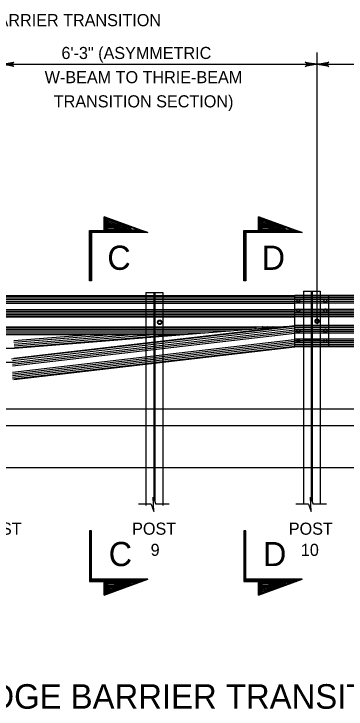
# Model space of a CAD drawing. Extents: x 632007860 to 635435983, y 295418622 to 297794622.
# Drawn here: x 632367530 to 632449960, y 296174617 to 296347078 of the extents above; entities that cross this region are included whole.
import ezdxf

# ---------------------------------------------------------------- set-up
doc = ezdxf.new("R2010")
doc.units = 0
for name, color, linetype in [('S-ABUT', 7, 'Continuous'), ('S-DETL-DIMS', 7, 'Continuous'), ('S-DETL-T120', 7, 'Continuous'), ('S-DETL-T175', 7, 'Continuous'), ('S-DETL-T240', 7, 'Continuous'), ('S-GRND-MAJR', 7, 'Continuous'), ('S-MISC-CNTR-WT01', 7, 'Continuous'), ('S-STEL', 7, 'Continuous')]:
    doc.layers.add(name, color=color, linetype=linetype)

msp = doc.modelspace()

# ---------------------------------------------------------------- linework, layer by layer
at = {"layer": 'S-ABUT'}
for p, q in [((632118834, 296249115), (632656122, 296249115)), ((632141627, 296234532), (632656122, 296234532))]:
    msp.add_line(p, q, dxfattribs=at)
at = {"layer": 'S-DETL-DIMS'}
for p, q in [((632130592, 296334582), (632596456, 296334582)), ((632401549, 296225427), (632398423, 296225427)), ((632406049, 296225427), (632402720, 296225427)), ((632440609, 296225427), (632437484, 296225427)), ((632445109, 296225427), (632441781, 296225427))]:
    msp.add_line(p, q, dxfattribs=at)
for points in [[(632364632, 296334582), (632367545, 296335128), (632367320, 296334973), (632367205, 296334778), (632367171, 296334582), (632367205, 296334387), (632367320, 296334192), (632367545, 296334036), (632364632, 296334582), (632367320, 296334192), (632367205, 296334387), (632364632, 296334582), (632367171, 296334582), (632367205, 296334778), (632364632, 296334582), (632367320, 296334973)], [(632442753, 296334582), (632439841, 296334036), (632440065, 296334192), (632440181, 296334387), (632440214, 296334582), (632440181, 296334778), (632440065, 296334973), (632439841, 296335128), (632442753, 296334582), (632440065, 296334973), (632440181, 296334778), (632442753, 296334582), (632440214, 296334582), (632440181, 296334387), (632442753, 296334582), (632440065, 296334192)], [(632442753, 296334582), (632445666, 296335128), (632445441, 296334973), (632445326, 296334778), (632445292, 296334582), (632445326, 296334387), (632445441, 296334192), (632445666, 296334036), (632442753, 296334582), (632445441, 296334192), (632445326, 296334387), (632442753, 296334582), (632445292, 296334582), (632445326, 296334778), (632442753, 296334582), (632445441, 296334973)], [(632386546, 296280833), (632386546, 296293072), (632400021, 296293072), (632400737, 296292812), (632386807, 296292812), (632386807, 296280833), (632386286, 296280833), (632386286, 296293332), (632399306, 296293332), (632389931, 296296745), (632389931, 296293332), (632400737, 296292812), (632390267, 296296326), (632390244, 296293583), (632398247, 296293493), (632390549, 296295965), (632390549, 296293876), (632396644, 296293786), (632390843, 296295592), (632390854, 296294192), (632395583, 296293955), (632391125, 296295197), (632391136, 296294452), (632394184, 296294204), (632391373, 296294937), (632391407, 296294621), (632393066, 296294430), (632391379, 296294782), (632389931, 296296745), (632389931, 296293332), (632391407, 296294621), (632400737, 296292812)], [(632424835, 296280833), (632424835, 296293072), (632438310, 296293072), (632439026, 296292812), (632425095, 296292812), (632425095, 296280833), (632424575, 296280833), (632424575, 296293332), (632437595, 296293332), (632428220, 296296745), (632428220, 296293332), (632439026, 296292812), (632428556, 296296326), (632428533, 296293583), (632436536, 296293493), (632428838, 296295965), (632428838, 296293876), (632434933, 296293786), (632429131, 296295592), (632429143, 296294192), (632433872, 296293955), (632429414, 296295197), (632429425, 296294452), (632432473, 296294204), (632429662, 296294937), (632429696, 296294621), (632431355, 296294430), (632429668, 296294782), (632428220, 296296745), (632428220, 296293332), (632429696, 296294621), (632439026, 296292812)], [(632401549, 296225427), (632402262, 296223669), (632402049, 296227184), (632402720, 296225427)], [(632440609, 296225427), (632441323, 296223669), (632441110, 296227184), (632441781, 296225427)], [(632386546, 296218805), (632386546, 296206566), (632400021, 296206566), (632400737, 296206826), (632386807, 296206826), (632386807, 296218805), (632386286, 296218805), (632386286, 296206305), (632399306, 296206305), (632389931, 296202893), (632389931, 296206305), (632400737, 296206826), (632390267, 296203312), (632390244, 296206055), (632398247, 296206145), (632390549, 296203673), (632390549, 296205761), (632396644, 296205852), (632390843, 296204046), (632390854, 296205445), (632395583, 296205682), (632391125, 296204441), (632391136, 296205186), (632394184, 296205434), (632391373, 296204700), (632391407, 296205016), (632393066, 296205208), (632391379, 296204856), (632389931, 296202893), (632389931, 296206305), (632391407, 296205016), (632400737, 296206826)], [(632424835, 296218805), (632424835, 296206566), (632438310, 296206566), (632439026, 296206826), (632425095, 296206826), (632425095, 296218805), (632424575, 296218805), (632424575, 296206305), (632437595, 296206305), (632428220, 296202893), (632428220, 296206305), (632439026, 296206826), (632428556, 296203312), (632428533, 296206055), (632436536, 296206145), (632428838, 296203673), (632428838, 296205761), (632434933, 296205852), (632429131, 296204046), (632429143, 296205445), (632433872, 296205682), (632429414, 296204441), (632429425, 296205186), (632432473, 296205434), (632429662, 296204700), (632429696, 296205016), (632431355, 296205208), (632429668, 296204856), (632428220, 296202893), (632428220, 296206305), (632429696, 296205016), (632439026, 296206826)]]:
    msp.add_lwpolyline(points, dxfattribs=at)
for points in [[(632386807, 296280833), (632386286, 296280833), (632386286, 296293332), (632389931, 296293332), (632389931, 296296745), (632400737, 296292812), (632386807, 296292812)], [(632425095, 296280833), (632424575, 296280833), (632424575, 296293332), (632428220, 296293332), (632428220, 296296745), (632439026, 296292812), (632425095, 296292812)], [(632386807, 296218805), (632386286, 296218805), (632386286, 296206305), (632389931, 296206305), (632389931, 296202893), (632400737, 296206826), (632386807, 296206826)], [(632425095, 296218805), (632424575, 296218805), (632424575, 296206305), (632428220, 296206305), (632428220, 296202893), (632439026, 296206826), (632425095, 296206826)]]:
    msp.add_lwpolyline(points, close=True, dxfattribs=at)
at = {"layer": 'S-GRND-MAJR'}
msp.add_line((632118834, 296244949), (632656122, 296244949), dxfattribs=at)
at = {"layer": 'S-MISC-CNTR-WT01'}
for p, q in [((632442753, 296270859), (632442753, 296337520)), ((632442753, 296271714), (632442753, 296270148)), ((632439264, 296266278), (632443559, 296266278))]:
    msp.add_line(p, q, dxfattribs=at)
at = {"layer": 'S-STEL'}
for p, q in [((632400302, 296277997), (632404470, 296277997)), ((632400302, 296277997), (632400302, 296276955)), ((632402256, 296277997), (632402256, 296226558)), ((632402516, 296277997), (632402516, 296226047)), ((632404470, 296277997), (632404470, 296276955)), ((632439363, 296278280), (632443530, 296278280)), ((632439363, 296278280), (632439363, 296277238)), ((632441317, 296278280), (632441317, 296226558)), ((632441577, 296278280), (632441577, 296226047)), ((632443530, 296278280), (632443530, 296277238)), ((632118834, 296277239), (632437249, 296277239)), ((632118834, 296277070), (632437249, 296277070)), ((632118834, 296276648), (632437249, 296276648)), ((632118834, 296276227), (632437249, 296276227)), ((632400302, 296276955), (632400302, 296260215)), ((632404470, 296276955), (632404470, 296260699)), ((632647109, 296276648), (632437222, 296276648)), ((632647109, 296277239), (632437249, 296277239)), ((632437249, 296271927), (632437249, 296277239)), ((632647109, 296277070), (632437249, 296277070)), ((632647109, 296276648), (632437249, 296276648)), ((632647109, 296276227), (632437249, 296276227)), ((632437949, 296276227), (632438267, 296276227)), ((632439363, 296277238), (632439363, 296264508)), ((632443530, 296277238), (632443530, 296264508)), ((632444944, 296276227), (632444626, 296276227)), ((632445644, 296264508), (632445644, 296277239)), ((632118834, 296275721), (632437249, 296275721)), ((632118834, 296275299), (632437249, 296275299)), ((632647389, 296275721), (632437249, 296275721)), ((632647007, 296275299), (632437249, 296275299)), ((632438284, 296275444), (632437966, 296275444)), ((632444658, 296275444), (632444976, 296275444)), ((632118834, 296273782), (632437249, 296273782)), ((632118834, 296273360), (632437249, 296273360)), ((632118834, 296272939), (632437249, 296272939)), ((632118834, 296272517), (632437249, 296272517)), ((632647109, 296273782), (632437249, 296273782)), ((632647109, 296273360), (632437249, 296273360)), ((632647109, 296272939), (632437249, 296272939)), ((632647109, 296272517), (632437249, 296272517)), ((632438267, 296273023), (632437949, 296273023)), ((632437966, 296273821), (632438284, 296273821)), ((632444976, 296273821), (632444658, 296273821)), ((632444658, 296273039), (632444976, 296273039)), ((632118834, 296272096), (632437249, 296272096)), ((632118834, 296271965), (632437249, 296271927)), ((632403809, 296271045), (632403576, 296271045)), ((632403809, 296271045), (632403576, 296271045)), ((632647109, 296272096), (632437249, 296272096)), ((632647109, 296271927), (632437249, 296271927)), ((632437249, 296269819), (632437249, 296271927)), ((632442171, 296270862), (632442171, 296270854)), ((632442171, 296270862), (632442171, 296270854)), ((632442869, 296271328), (632442637, 296271328)), ((632442869, 296271328), (632442637, 296271328)), ((632443335, 296270854), (632443335, 296270862)), ((632443335, 296270854), (632443335, 296270862)), ((632118834, 296269483), (632433852, 296269483)), ((632118834, 296269315), (632427667, 296269315)), ((632366933, 296261480), (632437249, 296269651)), ((632367184, 296261088), (632437249, 296269229)), ((632367523, 296261678), (632437249, 296269819)), ((632367653, 296264161), (632435417, 296269606)), ((632403111, 296270579), (632403111, 296270571)), ((632403111, 296270579), (632403111, 296270571)), ((632403576, 296270106), (632403809, 296270106)), ((632403576, 296270106), (632403809, 296270106)), ((632404274, 296270571), (632404274, 296270579)), ((632404274, 296270571), (632404274, 296270579)), ((632647109, 296269819), (632437249, 296269819)), ((632437249, 296264508), (632437249, 296269819)), ((632647109, 296269651), (632437249, 296269651)), ((632647109, 296269229), (632437249, 296269229)), ((632442637, 296270389), (632442869, 296270389)), ((632442637, 296270389), (632442869, 296270389)), ((632118834, 296268893), (632426548, 296268893)), ((632118834, 296268471), (632421302, 296268471)), ((632118834, 296267966), (632415005, 296267966)), ((632118834, 296267544), (632409759, 296267544)), ((632367184, 296260160), (632437249, 296268302)), ((632367184, 296259739), (632437249, 296267880)), ((632367503, 296266025), (632386412, 296267544)), ((632367537, 296265606), (632391659, 296267544)), ((632367570, 296265187), (632396905, 296267544)), ((632367604, 296264768), (632402152, 296267544)), ((632367638, 296264350), (632407399, 296267544)), ((632367909, 296260666), (632437249, 296268723)), ((632647109, 296268723), (632437249, 296268723)), ((632647454, 296268302), (632437249, 296268302)), ((632647045, 296267880), (632437249, 296267880)), ((632437929, 296268794), (632438247, 296268794)), ((632438287, 296268011), (632437969, 296268011)), ((632444976, 296268794), (632444658, 296268794)), ((632444658, 296268011), (632444976, 296268011)), ((632367184, 296258221), (632437037, 296266338)), ((632367184, 296257800), (632437085, 296265922)), ((632647109, 296266363), (632437249, 296266363)), ((632647109, 296265941), (632437249, 296265941)), ((632437949, 296266363), (632438267, 296266363)), ((632438267, 296265604), (632437949, 296265604)), ((632438287, 296266388), (632437969, 296266388)), ((632444626, 296265604), (632444944, 296265604)), ((632444976, 296266388), (632444658, 296266388)), ((632118834, 296264161), (632367653, 296264161)), ((632367184, 296257378), (632437133, 296265506)), ((632367184, 296256957), (632437182, 296265090)), ((632367184, 296256535), (632437230, 296264674)), ((632367523, 296256406), (632437249, 296264508)), ((632647109, 296265520), (632437249, 296265520)), ((632647109, 296265098), (632437249, 296265098)), ((632647109, 296264677), (632437249, 296264677)), ((632647109, 296264508), (632437249, 296264508)), ((632439363, 296264508), (632439363, 296244948)), ((632443530, 296264508), (632443530, 296244948)), ((632118834, 296260666), (632367909, 296260666)), ((632404470, 296260699), (632404470, 296244665)), ((632400302, 296260215), (632400302, 296244665)), ((632439363, 296244948), (632439363, 296225426)), ((632443530, 296244948), (632443530, 296225426)), ((632400302, 296244665), (632400302, 296225143)), ((632404470, 296244665), (632404470, 296225143))]:
    msp.add_line(p, q, dxfattribs=at)
for centre in [(632403692, 296270575), (632442753, 296270858)]:
    msp.add_circle(centre, 391, dxfattribs=at)
for centre, radius, start, end in [((632403576, 296270579), 466, 90, 180), ((632403576, 296270579), 466, 90, 180), ((632403809, 296270579), 466, 0, 90), ((632403809, 296270579), 466, 0, 90), ((632442637, 296270862), 466, 90, 180), ((632442637, 296270862), 466, 90, 180), ((632442637, 296270854), 466, 180, 270), ((632442637, 296270854), 466, 180, 270), ((632442869, 296270862), 466, 0, 90), ((632442869, 296270862), 466, 0, 90), ((632442869, 296270854), 466, 270, 360), ((632442869, 296270854), 466, 270, 360), ((632403576, 296270571), 466, 180, 270), ((632403576, 296270571), 466, 180, 270), ((632403809, 296270571), 466, 270, 360), ((632403809, 296270571), 466, 270, 360), ((632427422, 296269226), 261, 279.51241, 80.8982), ((632429123, 296269292), 195, 279.51241, 80.8982), ((632430422, 296269343), 140, 279.51241, 80.8982), ((632431782, 296269399), 85.8, 278.65289, 80.03868)]:
    msp.add_arc(centre, radius, start, end, dxfattribs=at)
for centre, major_axis, start_param, end_param in [((632437966, 296275835), (0, -391), 3.1395093, 6.2852686), ((632438261, 296275835), (0, 391), 3.1395093, 6.2852686), ((632444657, 296275835), (0, 391), 6.281102, 9.4268613), ((632444953, 296275835), (0, -391), 6.281102, 9.4268613), ((632437966, 296273430), (0, -391), 3.1395093, 6.2852686), ((632438261, 296273430), (0, 391), 3.1395093, 6.2852686), ((632444657, 296273430), (0, 391), 6.281102, 9.4268613), ((632444953, 296273430), (0, -391), 6.281102, 9.4268613), ((632437966, 296268403), (0, -391), 3.1395093, 6.2852686), ((632438261, 296268403), (0, 391), 3.1395093, 6.2852686), ((632444657, 296268403), (0, 391), 6.281102, 9.4268613), ((632444953, 296268403), (0, -391), 6.281102, 9.4268613), ((632437966, 296265997), (0, -391), 3.1395093, 6.2852686), ((632438261, 296265997), (0, 391), 3.1395093, 6.2852686), ((632444657, 296265997), (0, 391), 6.281102, 9.4268613), ((632444953, 296265997), (0, -391), 6.281102, 9.4268613)]:
    msp.add_ellipse(centre, major_axis=major_axis, ratio=0.7543445, start_param=start_param, end_param=end_param, dxfattribs=at)

# ---------------------------------------------------------------- texts
at = {"layer": 'S-DETL-T120'}
for s, height, p in [('PAY LIMIT FOR THRIE-BEAM GUIDE RAIL TO BRIDGE BARRIER TRANSITION', 2999.85, (632257828, 296344033)), (' 6\'-3" (ASYMMETRIC', 2999.85, (632378218, 296335889)), ('W-BEAM TO THRIE-BEAM', 2999.85, (632375171, 296329889)), ('TRANSITION SECTION)', 2999.85, (632377427, 296323889)), ('POST', 2999.8, (632358510, 296217875)), ('POST', 2999.8, (632396866, 296217875)), ('POST', 2999.8, (632435745, 296217875)), ('9', 3000, (632401460, 296212625)), ('10', 2999.8, (632438733, 296212625))]:
    msp.add_text(s, height=height, dxfattribs=at).set_placement(p)
at = {"layer": 'S-DETL-T175'}
msp.add_text('ELEVATION VIEW FOR THRIE-BEAM GUIDE RAIL TO BRIDGE BARRIER TRANSITION WITH CURB', height=6096, dxfattribs=at).set_placement((632142927, 296174703))
at = {"layer": 'S-DETL-T240'}
for s, p in [('C', (632390713, 296283584)), ('D', (632429002, 296283584)), ('C', (632391052, 296210083)), ('D', (632429341, 296210083))]:
    msp.add_text(s, height=6000, dxfattribs=at).set_placement(p)

doc.saveas('drawing.dxf')
